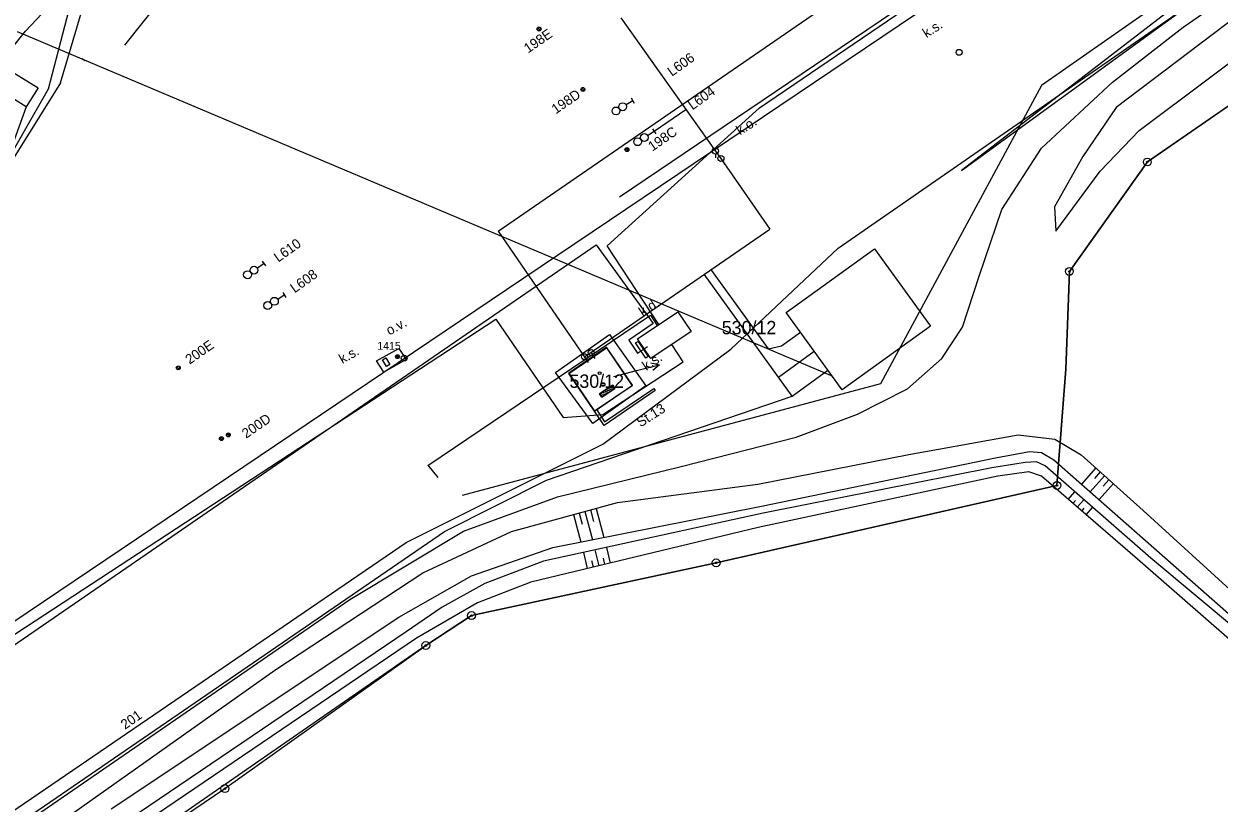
# Model space of a CAD drawing. Extents: x -469926 to -462499, y -1098642 to -1092733.
# Drawn here: x -467650 to -467497.6, y -1097002.4 to -1096903 of the extents above; entities that cross this region are included whole.
import ezdxf

# ---------------------------------------------------------------- set-up
doc = ezdxf.new("R2010")
doc.units = 0
for name, color, linetype in [('Vrstva 1', 7, 'Continuous'), ('Vrstva 10', 7, 'Continuous'), ('Vrstva 11', 7, 'Continuous'), ('Vrstva 12', 7, 'Continuous'), ('Vrstva 13', 7, 'Continuous'), ('Vrstva 16', 7, 'Continuous'), ('Vrstva 17', 7, 'Continuous'), ('Vrstva 18', 7, 'Continuous'), ('Vrstva 19', 7, 'Continuous'), ('Vrstva 20', 7, 'Continuous'), ('Vrstva 24', 7, 'Continuous'), ('Vrstva 25', 7, 'Continuous'), ('Vrstva 42', 7, 'Continuous'), ('Vrstva 44', 7, 'Continuous'), ('Vrstva 46', 7, 'Continuous'), ('Vrstva 48', 7, 'Continuous'), ('Vrstva 50', 7, 'Continuous'), ('Vrstva 51', 7, 'Continuous'), ('Vrstva 52', 7, 'Continuous'), ('Vrstva 58', 7, 'Continuous'), ('Vrstva 6', 7, 'Continuous'), ('Vrstva 62', 7, 'Continuous'), ('Vrstva 7', 7, 'Continuous'), ('Vrstva 8', 7, 'Continuous'), ('Vrstva 9', 7, 'Continuous')]:
    doc.layers.add(name, color=color, linetype=linetype)

msp = doc.modelspace()

# ---------------------------------------------------------------- linework, layer by layer
at = {"layer": 'Vrstva 1'}
for p, q in [((-467494.06, -1096892.54), (-467520.26, -1096910.87)), ((-467506.78, -1096920.64), (-467472.82, -1096897.14)), ((-467520.26, -1096910.87), (-467540.79, -1096948.95)), ((-467516.72, -1096934.6), (-467506.78, -1096920.64)), ((-467517.16, -1096947.08), (-467516.72, -1096934.6)), ((-467575.72, -1096944.27), (-467580.51, -1096947.59)), ((-467572.39, -1096949.12), (-467575.72, -1096944.27)), ((-467517.56, -1096951.98), (-467517.16, -1096947.08)), ((-467580.51, -1096947.59), (-467577.22, -1096952.43)), ((-467540.79, -1096948.95), (-467594.08, -1096963.17)), ((-467577.22, -1096952.43), (-467572.39, -1096949.12)), ((-467518.3, -1096961.89), (-467517.56, -1096951.98)), ((-467561.73, -1096971.75), (-467518.3, -1096961.89)), ((-467592.91, -1096978.48), (-467561.73, -1096971.75)), ((-467598.73, -1096982.29), (-467592.91, -1096978.48)), ((-467624.34, -1097000.54), (-467598.73, -1096982.29)), ((-467649.9, -1097017.76), (-467624.34, -1097000.54))]:
    msp.add_line(p, q, dxfattribs=at)
at = {"layer": 'Vrstva 10'}
msp.add_lwpolyline([(-467357.14, -1096816.33), (-467378.69, -1096831.58), (-467390.9, -1096840.3), (-467403.27, -1096848.26), (-467423.13, -1096862.44), (-467444.81, -1096877.16), (-467472.82, -1096897.14), (-467506.78, -1096920.64), (-467516.72, -1096934.6), (-467517.16, -1096947.08), (-467517.56, -1096951.98), (-467518.3, -1096961.89), (-467561.73, -1096971.75), (-467592.91, -1096978.48), (-467598.73, -1096982.29), (-467649.9, -1097017.76)], dxfattribs=at)
at = {"layer": 'Vrstva 11'}
for p, q in [((-467584.53, -1096903.78), (-467584.21, -1096903.46)), ((-467584.4, -1096903.92), (-467584.07, -1096903.59)), ((-467578.94, -1096911.48), (-467578.62, -1096911.16)), ((-467578.81, -1096911.62), (-467578.48, -1096911.29)), ((-467573.33, -1096919.15), (-467573, -1096918.83)), ((-467573.2, -1096919.29), (-467572.87, -1096918.96)), ((-467602.57, -1096945.56), (-467602.25, -1096945.24)), ((-467602.44, -1096945.7), (-467602.12, -1096945.37)), ((-467630.51, -1096946.99), (-467630.19, -1096946.66)), ((-467630.38, -1096947.12), (-467630.05, -1096946.79)), ((-467625.01, -1096956.01), (-467624.69, -1096955.68)), ((-467624.88, -1096956.14), (-467624.56, -1096955.81)), ((-467624.13, -1096955.53), (-467623.81, -1096955.21)), ((-467624, -1096955.67), (-467623.67, -1096955.34))]:
    msp.add_line(p, q, dxfattribs=at)
for centre in [(-467584.3, -1096903.69), (-467578.71, -1096911.39), (-467573.1, -1096919.06), (-467602.34, -1096945.47), (-467630.28, -1096946.89), (-467624.78, -1096955.91), (-467623.9, -1096955.44)]:
    msp.add_circle(centre, 0.25, dxfattribs=at)
at = {"layer": 'Vrstva 12'}
msp.add_lwpolyline([(-467649.65, -1096913.6), (-467651.54, -1096918.78), (-467655.32, -1096924.33)], dxfattribs=at)
for points in [[(-467571.75, -1096943.2), (-467566.62, -1096939.76), (-467564.93, -1096942.27), (-467570.06, -1096945.72)], [(-467572.01, -1096943.71), (-467571.69, -1096943.53), (-467570.41, -1096945.44), (-467570.71, -1096945.64)]]:
    msp.add_lwpolyline(points, close=True, dxfattribs=at)
at = {"layer": 'Vrstva 13'}
for points in [[(-467704.88, -1096983.2), (-467697.29, -1096972.53), (-467683.76, -1096952.91), (-467669.75, -1096933.63), (-467658.97, -1096915.46), (-467649.74, -1096903.94), (-467641.34, -1096894.98), (-467634.59, -1096886.79), (-467627.62, -1096876.3), (-467620.64, -1096867.78), (-467608.23, -1096855.59)], [(-467649.59, -1097004.79), (-467608.42, -1096976.41), (-467593.94, -1096967.7), (-467581.97, -1096963.32), (-467566.21, -1096959.48), (-467551.54, -1096955.72), (-467543.73, -1096952.79), (-467537.36, -1096949.55), (-467532.98, -1096945.68), (-467530.33, -1096941.69), (-467528.22, -1096935.22), (-467525.34, -1096926.69), (-467520.27, -1096918.88), (-467511.23, -1096910.45), (-467502.23, -1096903.47), (-467474.85, -1096884.54), (-467452, -1096868.89)]]:
    msp.add_lwpolyline(points, dxfattribs=at)
at = {"layer": 'Vrstva 16'}
for p, q in [((-467561.83, -1096919.62), (-467561.83, -1096920.12)), ((-467560.92, -1096920.51), (-467560.65, -1096920.93)), ((-467577.45, -1096945.27), (-467577.19, -1096945.7)), ((-467601.52, -1096945.65), (-467601.47, -1096945.65)), ((-467578.32, -1096945.79), (-467578.06, -1096946.21)), ((-467571.88, -1096947.25), (-467568.97, -1096946.52)), ((-467574.79, -1096947.99), (-467571.88, -1096947.25))]:
    msp.add_line(p, q, dxfattribs=at)
msp.add_lwpolyline([(-467570.06, -1096946.27), (-467568.97, -1096946.52), (-467569.82, -1096947.25)], dxfattribs=at)
for centre in [(-467561.83, -1096919.25), (-467561.12, -1096920.19), (-467601.49, -1096945.65), (-467578.52, -1096945.47), (-467577.65, -1096944.95)]:
    msp.add_circle(centre, 0.378, dxfattribs=at)
at = {"layer": 'Vrstva 18'}
for p, q in [((-467574.91, -1096949.09), (-467576.58, -1096950.19)), ((-467576.58, -1096950.19), (-467576.3, -1096950.61)), ((-467576.52, -1096950.15), (-467575.83, -1096950.3)), ((-467576.39, -1096949.05), (-467575.94, -1096949.15)), ((-467576.34, -1096948.86), (-467575.91, -1096948.95)), ((-467576.3, -1096950.61), (-467574.63, -1096949.51)), ((-467576.29, -1096950), (-467575.59, -1096950.14)), ((-467576.05, -1096949.84), (-467575.36, -1096949.99)), ((-467575.81, -1096949.69), (-467575.12, -1096949.83)), ((-467575.58, -1096949.53), (-467574.88, -1096949.68)), ((-467575.34, -1096949.38), (-467574.65, -1096949.52)), ((-467575.1, -1096949.22), (-467574.78, -1096949.29)), ((-467574.63, -1096949.51), (-467574.91, -1096949.09)), ((-467576.46, -1096950.37), (-467576.07, -1096950.45)), ((-467576.3, -1096950.61), (-467576.3, -1096950.61))]:
    msp.add_line(p, q, dxfattribs=at)
msp.add_lwpolyline([(-467574.91, -1096949.09), (-467574.63, -1096949.51), (-467576.3, -1096950.61), (-467576.58, -1096950.19)], close=True, dxfattribs=at)
msp.add_circle((-467576.15, -1096949.02), 0.248, dxfattribs=at)
msp.add_circle((-467576.15, -1096949.02), 0.248, dxfattribs=at)
at = {"layer": 'Vrstva 20'}
msp.add_lwpolyline([(-467898.53, -1097177.25), (-467898.92, -1097172.7), (-467750.16, -1097071.31), (-467710.1, -1097043.92), (-467659.44, -1097008.91), (-467601.25, -1096969.18), (-467576.17, -1096956.63), (-467559.87, -1096944.52), (-467546.18, -1096931.64), (-467506.1, -1096903.82), (-467451.19, -1096865.6), (-467389.34, -1096822.85), (-467331.14, -1096782.86), (-467269.83, -1096740.82), (-467245.75, -1096727.72), (-467237.39, -1096726.88), (-467228.65, -1096727.98), (-467203.72, -1096744.02), (-467183.73, -1096749.88), (-467175.02, -1096748.65), (-467161.6, -1096742.85), (-467144.51, -1096733.78)], dxfattribs=at)
at = {"layer": 'Vrstva 24'}
for p, q in [((-467573.22, -1096913.33), (-467572.37, -1096912.8)), ((-467572.57, -1096912.48), (-467572.17, -1096913.12)), ((-467569.84, -1096916.4), (-467569.43, -1096917.03)), ((-467570.47, -1096917.25), (-467569.63, -1096916.71)), ((-467619.61, -1096933.28), (-467619.18, -1096933.89)), ((-467620.22, -1096934.16), (-467619.4, -1096933.58)), ((-467617.61, -1096938.13), (-467616.77, -1096937.59)), ((-467616.97, -1096937.28), (-467616.57, -1096937.91))]:
    msp.add_line(p, q, dxfattribs=at)
for centre, radius in [((-467574.49, -1096914.13), 0.5), ((-467573.64, -1096913.6), 0.5), ((-467571.73, -1096918.06), 0.5), ((-467570.89, -1096917.52), 0.5), ((-467506.78, -1096920.64), 0.5), ((-467506.78, -1096920.64), 0.1), ((-467621.45, -1096935.02), 0.5), ((-467620.63, -1096934.44), 0.5), ((-467516.72, -1096934.6), 0.5), ((-467516.72, -1096934.6), 0.1), ((-467618.03, -1096938.4), 0.5), ((-467618.88, -1096938.94), 0.5), ((-467518.3, -1096961.89), 0.5), ((-467518.3, -1096961.89), 0.1), ((-467561.73, -1096971.75), 0.5), ((-467561.73, -1096971.75), 0.1), ((-467592.91, -1096978.48), 0.5), ((-467592.91, -1096978.48), 0.1), ((-467598.73, -1096982.29), 0.5), ((-467598.73, -1096982.29), 0.1), ((-467624.34, -1097000.54), 0.5), ((-467624.34, -1097000.54), 0.1)]:
    msp.add_circle(centre, radius, dxfattribs=at)
at = {"layer": 'Vrstva 25'}
msp.add_circle((-467576.58, -1096947.58), 0.175, dxfattribs=at)
at = {"layer": 'Vrstva 42'}
msp.add_line((-467650.83, -1096904.01), (-467547.08, -1096947.85), dxfattribs=at)
at = {"layer": 'Vrstva 44'}
for p, q in [((-467602.73, -1096862.61), (-467637.14, -1096905.75)), ((-467589.53, -1096929.48), (-467521.4, -1096882.55)), ((-467645.3, -1096910.55), (-467639.34, -1096890.54)), ((-467573.88, -1096902.27), (-467561.83, -1096919.25)), ((-467645.3, -1096910.55), (-467660.57, -1096935.02)), ((-467569.63, -1096916.71), (-467565.6, -1096913.93)), ((-467561.83, -1096919.25), (-467561.12, -1096920.19)), ((-467561.12, -1096920.19), (-467554.91, -1096929.21)), ((-467589.53, -1096929.48), (-467578.16, -1096946.01)), ((-467578.52, -1096945.47), (-467554.91, -1096929.21)), ((-467552.03, -1096950.49), (-467563.26, -1096934.95)), ((-467555.04, -1096944.48), (-467562.4, -1096934.29)), ((-467553.42, -1096944.09), (-467550.99, -1096942.34)), ((-467555.04, -1096944.48), (-467553.42, -1096944.09)), ((-467577.65, -1096944.95), (-467577.32, -1096945.44)), ((-467553.79, -1096948.06), (-467549.23, -1096944.77)), ((-467552.03, -1096950.49), (-467547.48, -1096947.2)), ((-467583.34, -1096961.22), (-467552.03, -1096950.49)), ((-467596.36, -1096967.75), (-467583.34, -1096961.22)), ((-467689.92, -1097031.93), (-467596.36, -1096967.75))]:
    msp.add_line(p, q, dxfattribs=at)
at = {"layer": 'Vrstva 46'}
for p, q in [((-467556.22, -1096913.72), (-467520.95, -1096889.76)), ((-467575.63, -1096931.32), (-467556.22, -1096913.72)), ((-467569.03, -1096941.38), (-467575.63, -1096931.32)), ((-467659.81, -1096986.55), (-467589.82, -1096940.68)), ((-467598.49, -1096959.33), (-467570.08, -1096940.16)), ((-467589.82, -1096940.68), (-467581.23, -1096953.22)), ((-467570.08, -1096940.16), (-467569.23, -1096941.51)), ((-467565.93, -1096946.11), (-467567.37, -1096943.91)), ((-467576.19, -1096952.85), (-467565.93, -1096946.11)), ((-467581.23, -1096953.22), (-467576.19, -1096952.85)), ((-467597.18, -1096960.88), (-467598.42, -1096959.29))]:
    msp.add_line(p, q, dxfattribs=at)
at = {"layer": 'Vrstva 48'}
for points in [[(-467513.35, -1096959.66), (-467515.19, -1096961.72)], [(-467512.23, -1096960.66), (-467514.06, -1096962.71)], [(-467512.79, -1096960.16), (-467513.53, -1096960.98)], [(-467511.11, -1096961.66), (-467512.94, -1096963.7)], [(-467511.67, -1096961.16), (-467512.4, -1096961.98)], [(-467516.85, -1096963.69), (-467516.01, -1096962.72)], [(-467516.28, -1096964.18), (-467515.94, -1096963.79)], [(-467515.71, -1096964.67), (-467514.88, -1096963.71)], [(-467579.2, -1096965.41), (-467578.82, -1096966.82)], [(-467578.48, -1096965.21), (-467577.51, -1096968.81)], [(-467577.75, -1096965.01), (-467577.36, -1096966.47)], [(-467577.03, -1096964.82), (-467576.03, -1096968.51)], [(-467515.14, -1096965.16), (-467514.81, -1096964.77)], [(-467514.57, -1096965.65), (-467513.75, -1096964.7)], [(-467579.93, -1096965.6), (-467578.98, -1096969.1)], [(-467575.19, -1096971.79), (-467575.67, -1096969.79)], [(-467578.11, -1096972.49), (-467578.6, -1096970.43)], [(-467577.38, -1096972.32), (-467577.58, -1096971.5)], [(-467576.65, -1096972.14), (-467577.14, -1096970.11)], [(-467575.92, -1096971.96), (-467576.11, -1096971.16)]]:
    msp.add_lwpolyline(points, dxfattribs=at)
at = {"layer": 'Vrstva 51'}
for p, q in [((-467646.81, -1096911.31), (-467643.96, -1096900.39)), ((-467588.44, -1096936.91), (-467534, -1096900.21)), ((-467653.59, -1096923.12), (-467646.81, -1096911.31)), ((-467670.55, -1096992.23), (-467588.44, -1096936.91))]:
    msp.add_line(p, q, dxfattribs=at)
at = {"layer": 'Vrstva 52'}
for p, q in [((-467625.24, -1096964.38), (-467577.02, -1096931.22)), ((-467577.02, -1096931.22), (-467569.74, -1096941.23)), ((-467569.74, -1096941.23), (-467572.88, -1096943.37)), ((-467572.88, -1096943.37), (-467571.74, -1096945.03)), ((-467571.74, -1096945.03), (-467570.5, -1096944.19)), ((-467673.46, -1096997.53), (-467625.24, -1096964.38))]:
    msp.add_line(p, q, dxfattribs=at)
at = {"layer": 'Vrstva 58'}
msp.add_lwpolyline([(-467898.53, -1097177.25), (-467898.92, -1097172.7), (-467750.16, -1097071.31), (-467710.1, -1097043.92), (-467659.44, -1097008.91), (-467601.25, -1096969.18), (-467576.17, -1096956.63), (-467559.87, -1096944.52), (-467546.18, -1096931.64), (-467506.1, -1096903.82), (-467451.19, -1096865.6), (-467389.34, -1096822.85), (-467331.14, -1096782.86), (-467269.83, -1096740.82), (-467245.75, -1096727.72), (-467237.39, -1096726.88), (-467228.65, -1096727.98), (-467203.72, -1096744.02)], dxfattribs=at)
at = {"layer": 'Vrstva 6'}
for points in [[(-467654.15, -1096910.79), (-467652.67, -1096908.4), (-467648.14, -1096911.17), (-467649.65, -1096913.6)], [(-467552.8, -1096939.84), (-467541.54, -1096931.7), (-467534.42, -1096941.57), (-467545.67, -1096949.7)], [(-467605, -1096945.99), (-467602.16, -1096944.42), (-467601.25, -1096945.84), (-467604.07, -1096947.45)], [(-467580.49, -1096947.6), (-467575.72, -1096944.34), (-467572.43, -1096949.17), (-467577.22, -1096952.43)], [(-467577.22, -1096952.43), (-467576.93, -1096952.24), (-467575.95, -1096953.78), (-467569.68, -1096949.52), (-467569.49, -1096949.8), (-467576.01, -1096954.25)]]:
    msp.add_lwpolyline(points, close=True, dxfattribs=at)
msp.add_lwpolyline([(-467582.21, -1096947.48), (-467575.33, -1096942.65), (-467570.68, -1096949.17), (-467577.46, -1096954), (-467582.21, -1096947.48)], dxfattribs=at)
msp.add_circle((-467530.77, -1096906.66), 0.375, dxfattribs=at)
at = {"layer": 'Vrstva 62'}
for points in [[(-467574.07, -1096925.09), (-467515.98, -1096885.83), (-467488.76, -1096867.14), (-467461.54, -1096848.45), (-467430.95, -1096827.43), (-467403.61, -1096809.03), (-467342.28, -1096766.57), (-467297.27, -1096735.74), (-467268.35, -1096716.08), (-467245.3, -1096699.97), (-467216.92, -1096680.92), (-467188.08, -1096660.73), (-467133.34, -1096623.43), (-467074.29, -1096582.95), (-466962.32, -1096505.44), (-466913.49, -1096472.16), (-466857.83, -1096433.81), (-466817.26, -1096406.01), (-466762.14, -1096367.77), (-466734.95, -1096348.87)], [(-467400, -1096829.26), (-467458.93, -1096870.32), (-467502.5, -1096900.23), (-467530.48, -1096921.72)], [(-467530.48, -1096921.72), (-467498.14, -1096898.16), (-467441.55, -1096859.12), (-467400, -1096830.27)], [(-467450.59, -1096870.9), (-467484.53, -1096893.8), (-467510.75, -1096913.68), (-467515.02, -1096919.96), (-467518.62, -1096926.36), (-467518.46, -1096929.45), (-467512.81, -1096921.81), (-467507.81, -1096916.61), (-467481.61, -1096896.93), (-467448.56, -1096873.94)], [(-467647.36, -1097006.29), (-467617.98, -1096985.44), (-467599.11, -1096973.02), (-467587.81, -1096967.74), (-467574.3, -1096964.08), (-467556.42, -1096961.71), (-467537.16, -1096957.92), (-467523.24, -1096955.42), (-467518.56, -1096955.98), (-467515.21, -1096958), (-467507.3, -1096965.07), (-467488.1, -1096982.58), (-467482.27, -1096988.84), (-467484.94, -1096991.46), (-467508.04, -1096971.28), (-467520.29, -1096960.72), (-467521.88, -1096960.15), (-467525.82, -1096960.69), (-467556.37, -1096967.24), (-467585.35, -1096974.24), (-467592.13, -1096976.84), (-467599.91, -1096981.34), (-467635.57, -1097005.53)], [(-467638.85, -1097003.12), (-467602.19, -1096978.67), (-467592.92, -1096973.42), (-467582.56, -1096969.82), (-467555.97, -1096964.51), (-467526.15, -1096958.37), (-467521.79, -1096957.56), (-467520.28, -1096957.69), (-467518.71, -1096958.62), (-467504.9, -1096970.77), (-467483.39, -1096989.69), (-467483.75, -1096990.04), (-467506.34, -1096971.16), (-467519.81, -1096959.4), (-467520.91, -1096958.89), (-467522.34, -1096958.97), (-467526.58, -1096959.66), (-467555.73, -1096965.42), (-467583.75, -1096971.56), (-467591.21, -1096974.41), (-467596.65, -1096977.4), (-467601.24, -1096980.54), (-467636.68, -1097004.58)]]:
    msp.add_lwpolyline(points, dxfattribs=at)
at = {"layer": 'Vrstva 8'}
for p, q in [((-467642.57, -1096907.45), (-467642.15, -1096907.72)), ((-467603.56, -1096946.03), (-467603.56, -1096946.03))]:
    msp.add_line(p, q, dxfattribs=at)
msp.add_lwpolyline([(-467603.31, -1096946.46), (-467603.74, -1096946.71), (-467604.24, -1096945.85), (-467603.81, -1096945.6), (-467603.31, -1096946.46)], dxfattribs=at)

# ---------------------------------------------------------------- texts
at = {"layer": 'Vrstva 11'}
for s, p in [('198E', (-467585.7, -1096906.82)), ('198D', (-467582.17, -1096914.58)), ('198C', (-467569.86, -1096919.33)), ('200E', (-467628.84, -1096946.5)), ('200D', (-467621.63, -1096955.94)), ('201', (-467637.07, -1096993.05))]:
    msp.add_text(s, height=1.25, rotation=34.5693, dxfattribs=at).set_placement(p)
at = {"layer": 'Vrstva 17'}
msp.add_text('1415', height=1, dxfattribs=at).set_placement((-467604.91, -1096944.58))
at = {"layer": 'Vrstva 19'}
msp.add_text('St.13', height=1.25, rotation=32.4444, dxfattribs=at).set_placement((-467571.37, -1096954.5))
at = {"layer": 'Vrstva 25'}
for s, p in [('L606', (-467567.38, -1096909.78)), ('L604', (-467564.76, -1096914.07)), ('L610', (-467617.54, -1096933.48)), ('L608', (-467615.45, -1096937.4))]:
    msp.add_text(s, height=1.25, rotation=35.3878, dxfattribs=at).set_placement(p)
at = {"layer": 'Vrstva 50'}
for p in [(-467561.02, -1096942.61), (-467580.43, -1096949.44)]:
    msp.add_text('530/12', height=1.7, dxfattribs=at).set_placement(p)
at = {"layer": 'Vrstva 7'}
msp.add_text('o.v.', height=1.25, rotation=28.422, dxfattribs=at).set_placement((-467603.38, -1096942.78))
at = {"layer": 'Vrstva 9'}
for s, rotation, p in [('k.s.', 32.9883, (-467534.92, -1096904.87)), ('k.o.', 32.1439, (-467558.69, -1096917.26)), ('k.d.', 33.7132, (-467571.07, -1096940.41)), ('k.s.', 29.5128, (-467609.37, -1096946.41)), ('k.s.', 33.707, (-467570.64, -1096947.31))]:
    msp.add_text(s, height=1.25, rotation=rotation, dxfattribs=at).set_placement(p)

doc.saveas('drawing.dxf')
